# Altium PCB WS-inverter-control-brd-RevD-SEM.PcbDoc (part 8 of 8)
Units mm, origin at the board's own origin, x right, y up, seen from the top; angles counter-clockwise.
Board outline 270 x 105.92 mm, 6 copper layers (Top Layer, Int1 (Sign), Int2 (PWR), Int3 (GND), Int4 (Sign), Bottom Layer), stack 1.509 mm thick; 709 components, 375 nets, 2377 pads, 1332 vias.
Unrouted connection lines stored in the file: 55.
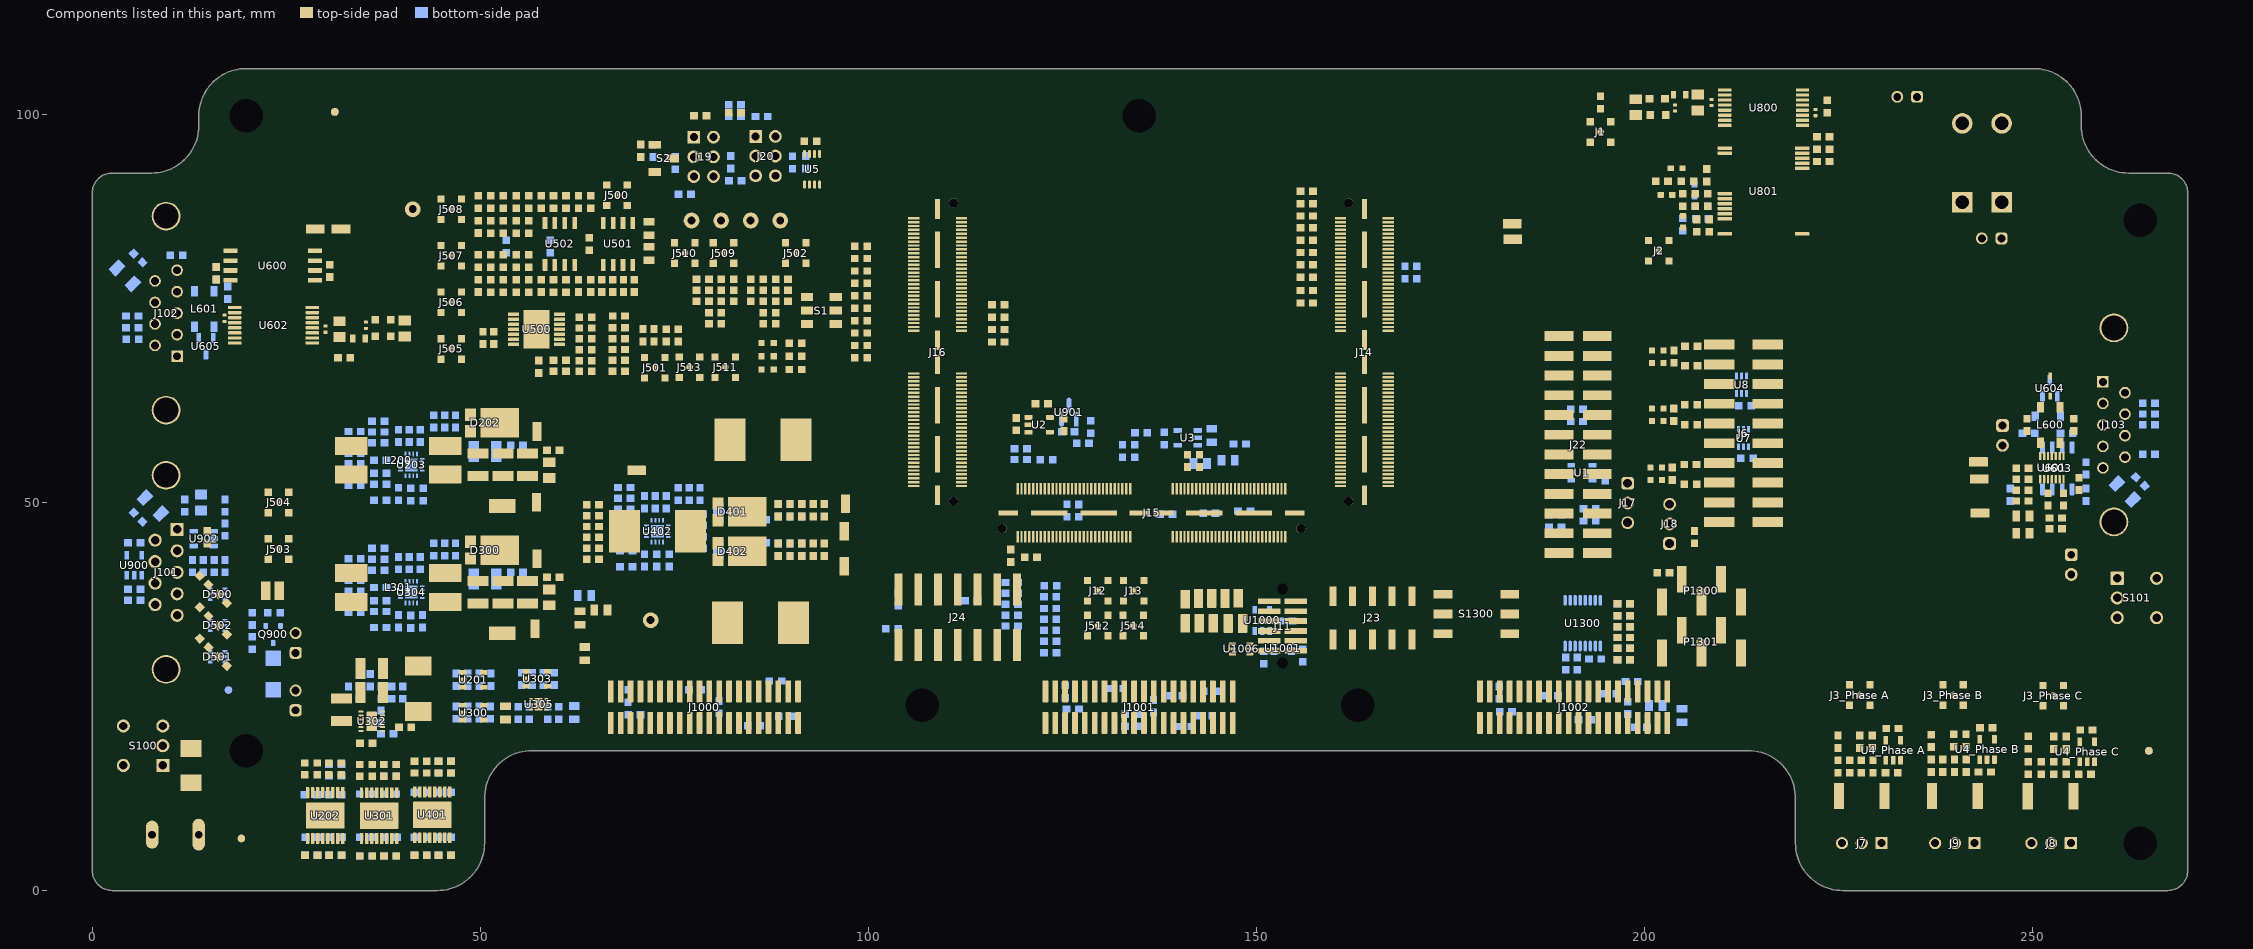
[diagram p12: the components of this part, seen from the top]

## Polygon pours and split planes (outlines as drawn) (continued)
GND on Top Layer "TOP_LAYER_GND_P448" (solid, remove dead copper, pour order 448): 29.692,48.725 30.942,47.475 57.192,47.475 61.192,51.475 61.192,59.475 56.692,63.975 31.192,63.975 29.692,62.475
+3.3V on Top Layer "TOP_LAYER_+3.3V_P446" (solid, remove dead copper, pour order 446): 183.868,55.069 188.268,55.069 188.268,56.04 183.868,56.04
NetD3_1 on Top Layer "TOP_LAYER_NETD3_1_P443" (solid, remove dead copper, pour order 443): 183.943,59.636 183.943,56.936 184.864,56.936 184.864,59.636
NetD2_1 on Top Layer "TOP_LAYER_NETD2_1_P444" (solid, remove dead copper, pour order 444): 185.643,59.636 185.643,56.936 186.605,56.936 186.605,59.636
NetD1_1 on Top Layer "TOP_LAYER_NETD1_1_P445" (solid, remove dead copper, pour order 445): 187.343,59.636 187.343,56.936 188.278,56.936 188.278,59.636
NetC606_1 on Top Layer "TOP_LAYER_NETC606_1_P441" (solid, remove dead copper, pour order 441): 27.493,72.066 27.493,71.006 29.193,71.006 29.193,72.066
+5V_ISO on Top Layer "TOP_LAYER_+5V_ISO_P436" (solid, remove dead copper, pour order 436): 17.493,75.267 17.493,73.656 19.193,73.656 19.193,75.267
NetC800_1 on Top Layer "TOP_LAYER_NETC800_1_P434" (solid, remove dead copper, pour order 434): 209.515,102.701 209.515,101.683 209.535,101.662 211.186,101.662 211.186,102.694
Pgndin_1 on Top Layer "TOP_LAYER_PGNDIN_1_P432" (solid, remove dead copper, pour order 432): 218.85,104.554 218.85,92.136 247.763,92.136 247.763,104.539
5V_iso_AMC_9 on Top Layer "TOP_LAYER_5V_ISO_AMC_9_P431" (solid, remove dead copper, pour order 431): 219.515,100.079 221.186,100.079 221.186,98.398 219.515,98.398
+5V on Top Layer "TOP_LAYER_+5V_P369" (solid, remove dead copper, pour order 369): 54.083,29.081 54.351,29.35 57.114,29.35 57.383,29.081 57.383,27.6 54.083,27.6
+5V on Top Layer "TOP_LAYER_+5V_P372" (solid, remove dead copper, pour order 372): 54.169,24.994 54.25,25.075 56.65,25.075 56.85,24.875 56.85,23.475 56.55,23.175 54.25,23.175 54.169,23.256
+3.3V_C-V on Top Layer "TOP_LAYER_+3.3V_C-V_P374" (solid, remove dead copper, pour order 374): 231.55,19.325 231.575,19.325 232.45,20.2 233.775,20.2 233.775,18.525 233.5,18.25 231.55,18.25 231.55,18.463
NetC411_1 on Top Layer "TOP_LAYER_NETC411_1_P376" (solid, remove dead copper, pour order 376): 73.475,47.625 74.2,48.35 75.7,48.35 75.975,48.075 75.975,46.175 75.75,45.95 74.125,45.95 73.475,46.6
+12V_H on Top Layer "TOP_LAYER_+12V_H_P377" (solid, pour order 377): 27.6,11.763 27.5,11.863 27.5,13.963 28.4,15.063 28.4,17.763 28.7,18.063 30.8,18.063 31,17.863 31,14.463 30.8,14.263 29,14.263 28.6,13.863 28.6,11.863 28.5,11.763
+12V_L on Top Layer "TOP_LAYER_+12V_L_P378" (solid, pour order 378): 34.557,11.743 34.457,11.843 34.457,13.943 35.357,15.043 35.357,17.743 35.657,18.043 37.857,18.043 38.157,17.743 38.157,14.198 38.102,14.143 35.857,14.143 35.557,13.843 35.557,11.843 35.457,11.743
+12V_LEM on Top Layer "TOP_LAYER_+12V_LEM_P379" (solid, pour order 379): 41.4,11.843 41.3,11.943 41.3,14.043 42.5,15.509 42.5,17.843 42.8,18.143 44.9,18.143 45.2,17.843 45.2,14.498 44.944,14.243 42.7,14.243 42.4,13.943 42.4,11.943 42.3,11.843
+12V_H on Top Layer "TOP_LAYER_+12V_H_P380" (solid, remove dead copper, pour order 380): 30.3,60.15 33.9,60.15 35.6,58.45 35.6,56.05 34.8,55.25 30.3,55.25
GND on Top Layer "TOP_LAYER_GND_P382" (solid, remove dead copper, pour order 382): 29.75,48.75 31,47.5 57.25,47.5 61.25,51.5 61.25,59.5 56.75,64 31.25,64 29.75,62.5
+12V_L on Top Layer "TOP_LAYER_+12V_L_P383" (solid, remove dead copper, pour order 383): 30.3,43.75 33.8,43.75 35.5,42.05 35.5,39.65 34.7,38.85 30.3,38.85
+12V_LEM on Top Layer "TOP_LAYER_+12V_LEM_P384" (solid, remove dead copper, pour order 384): 64.4,50.8 65.2,51.6 66.1,51.6 68.8,48.9 68.8,43.8 65.9,40.9 65.2,40.9 64.4,41.7
NetC411_2 on Top Layer "TOP_LAYER_NETC411_2_P385" (solid, remove dead copper, pour order 385): 79,59.9 80.3,61.2 84,61.2 84.42,60.78 84.42,49.82 81.6,47 79.9,47 79,47.9
+15V on Top Layer "TOP_LAYER_+15V_P386" (solid, remove dead copper, pour order 386): 81.7,50.5 82.4,51.2 97.7,51.2 97.9,51 97.9,48.929 97.871,48.9 89.1,48.9 86.6,46.4 83,46.4 81.7,47.7
NetC430_2 on Top Layer "TOP_LAYER_NETC430_2_P389" (solid, remove dead copper, pour order 389): 79.1,32.3 79.1,45.3 79.9,46.1 81.8,46.1 84.6,43.3 84.6,32.3 83.5,31.2 80.2,31.2
GND on Top Layer "TOP_LAYER_GND_P390" (solid, remove dead copper, pour order 390): 62.32,39.5 78.75,39.5 78.75,30.8 87.743,30.731 87.743,43.6 98.107,43.6 99.943,45.436 99.943,57.307 94.5,62.75 68.75,62.75 62.32,56.32
+3.3V_C-V_LDO on Top Layer "TOP_LAYER_+3.3V_C-V_LDO_P398" (solid, remove dead copper, pour order 398): 58.05,24.875 58.25,25.075 60.65,25.075 60.85,24.875 60.85,23.475 60.55,23.175 58.25,23.175 58.05,23.375
+3.3V_L on Top Layer "TOP_LAYER_+3.3V_L_P399" (solid, remove dead copper, pour order 399): 49.783,24.842 49.983,25.042 53.658,25.042 53.948,24.752 53.948,23.261 53.829,23.142 49.983,23.142 49.783,23.342
+12V_L on Top Layer "TOP_LAYER_+12V_L_P400" (solid, remove dead copper, pour order 400): 45.475,24.675 45.7,24.9 48.05,24.9 48.275,24.675 48.275,23.25 47.975,22.95 45.675,22.95 45.475,23.15
+3.3V_H on Top Layer "TOP_LAYER_+3.3V_H_P401" (solid, remove dead copper, pour order 401): 49.5,29.25 49.7,29.45 52.575,29.45 52.775,29.25 52.775,27.75 52.575,27.55 49.7,27.55 49.5,27.75
+12V_H on Top Layer "TOP_LAYER_+12V_H_P404" (solid, remove dead copper, pour order 404): 45.5,29.25 45.7,29.45 48.1,29.45 48.3,29.25 48.3,27.85 48,27.55 45.7,27.55 45.5,27.75
GND on Top Layer "TOP_LAYER_GND_P405" (solid, remove dead copper, pour order 405): 11.2,15.175 11.625,15.6 13.8,15.6 14.15,15.25 14.15,13.15 13.775,12.775 11.525,12.775 11.2,13.1
+3.3V_LDO on Top Layer "Top Layer-+3.3V" (solid, remove dead copper, pour order 417): 60.357,29.35 61.507,30.5 65.8,30.5 62.7,27.4 60.75,27.4 60.531,27.181 57.783,27.181 57.583,27.381 57.583,29.081 57.851,29.35
+3.3V on Top Layer "Top Layer-+3.3V" (solid, remove dead copper, pour order 418): 64.707,33.9 61.507,30.7 67.143,30.7 67.143,33.9
VIN_12V_1 on Top Layer "Top Layer-VIN_12V" (solid, remove dead copper, pour order 423): 6.2,4 9.6,0.6 47.5,0.6 48.1,1.2 48.1,4.6 47.682,5.018 44.119,5.018 43.05,6.087 43.05,7.448 41.3,7.448 41.3,4.918 37.277,4.918 36.207,5.987 36.207,7.348 34.457,7.348 34.457,5.038 30.125,5.038 29.25,5.913 29.25,7.363 27.5,7.363 21.816,7.363 16.3,12.88 16.3,18.2 14.5,20 8.3,20 6.2,17.9
5V_iso_AMC_9 on Top Layer "TOP_LAYER_5V_ISO_AMC_9_P429" (solid, remove dead copper, pour order 429): 219.5,100.059 221.2,100.059 221.2,98.447 221.151,98.398 221.137,98.412 219.515,98.412
GND on Int1 (Sign) "INT1_(SIGN)_GND_P491" (solid, remove dead copper, pour order 491): 27.134,105.918 27.134,57.836 23.834,54.536 0,54.536 0,-2.664 50.58,-2.664 50.58,9.063 59.053,17.536 214.034,17.536 217.796,13.774 217.796,4.774 224.134,-1.564 270.002,-1.564 270.002,75.673 211.641,75.673 211.641,105.918
GND_ISO on Int1 (Sign) "INT1_(SIGN)_GND_ISO_P503" (solid, pour order 503): 19.643,75.636 25.843,75.636 25.843,70.036 19.243,70.036 19.243,62.136 16.943,59.836 16.843,59.848 0.45,59.848 0.45,91.843 1.643,93.036 16.043,93.036 19.643,89.436
+3.3V_C-V on Int1 (Sign) "INT1_(SIGN)_+3.3V_C-V_P490" (solid, remove dead copper, pour order 490): 65.238,26.847 61.343,22.951 61.343,20.036 63.943,20.036 63.943,22.236 72.643,30.936 85.743,30.936 85.743,33.036 71.243,33.036
+5V on Int1 (Sign) "INT1_(SIGN)_+5V_P481" (solid, remove dead copper, pour order 481): 50.25,31.5 57.168,38.418 63.418,38.418 68.5,43.5 78.75,43.5 78.75,39.5 68.407,39.5 59.157,30.25 50.25,30.25
+3.3V on Int4 (Sign) "INT4_(SIGN)_+3.3V_P495" (solid, remove dead copper, pour order 495): 71.738,79.336 79.043,79.336 79.043,81.811 71.738,81.811
+5V on Int4 (Sign) "INT4_(SIGN)_+5V_P483" (solid, remove dead copper, pour order 483): 53.943,27.836 55.217,27.836 55.943,28.563 55.943,30.736 53.943,30.736
+5V on Int4 (Sign) "INT4_(SIGN)_+5V_P482" (solid, remove dead copper, pour order 482): 36.943,29.436 36.943,27.368 39.675,27.368 39.675,30.136 56.85,30.136 56.85,31.036 36.943,31.036
+5V on Int4 (Sign) "INT4_(SIGN)_+5V_P479" (solid, remove dead copper, pour order 479): 76.843,43.736 76.843,39.836 78.743,39.836 78.743,57.969 109.143,57.969 109.143,60.636 76.843,60.636

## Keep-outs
Top Layer:
  rectangle: 30.55,5.581 31.4,6.831
  rectangle: 37.507,5.561 38.357,6.811
  rectangle: 44.35,5.661 45.2,6.911
  lines w0.25: 26.613,75.909 26.613,76.136 28.771,76.136 31.643,76.136 33.243,74.536 41.379,74.536 ; 26.631,69.136 27.343,69.136 28.092,69.136 28.892,69.936 29.143,69.936 39.143,69.936 ; 199.743,98.936 204.84,98.939 206.843,96.936 211.964,96.936 212.136,97.109 212.136,98.036 ; 200.25,103.144 200.743,103.636 207.843,103.636 208.643,104.436 208.788,104.436 210.643,104.436 212.194,104.436
  lines w0.35: -1.351,59.536 17.626,59.536 19.943,61.853 19.943,89.536 16.443,93.036 7.943,93.036 ; -1.179,55.877 23.605,55.877 26.604,58.875 26.604,94.436 ; 212.043,107.036 212.043,76.735 212.242,76.536 272.743,76.536 ; 212.191,106.932 212.191,76.631 212.39,76.432 272.891,76.432 ; 218.85,91.835 229.173,91.835 231.874,94.536 256.443,94.536
  lines w0.5: 29.75,30.6 44.25,30.6 ; 32.7,18.1 29.75,21.05 29.75,29.25 29.75,32.75 29.75,34 29.75,38.75 29.75,46.25 31,47.5 ; 37.3,18.5 40.7,18.5 41.7,19.5 43,19.5 44.25,20.75 44.25,26.25 44.25,29.5 44.25,30.6 ; 61.25,57.002 63.002,57.002 68.75,62.75 94.5,62.75 94.85,62.4 100.25,57 100.25,51.25 100.25,48.5 ; 62.32,39.5 62.32,57.002 ; 99.25,39.5 93.5,33.75 93.5,30.664 86.75,30.664 86.75,39.25 85.75,39.25 85.25,39.25 85.25,30.75 78.75,30.75 78.75,34.25 78.75,39.5 76.25,39.5 65.107,39.5 61.25,39.5 ; 31,47.5 57.25,47.5 ; 31,47.5 29.75,48.75 29.75,62.5 31.25,64 56.75,64 59.5,61.25 61.25,59.5 61.25,53.75 61.25,51.5 59.75,50 57.25,47.5 ; 44.25,30.6 55.6,30.6 56.85,30.6 60,33.75 61.25,35 61.25,39.5 ; 57.25,47.5 61.25,43.5 61.25,39.5
Int2 (PWR):
  lines w0.35: -1.351,59.536 17.459,59.536 19.943,62.021 19.943,89.704 16.443,93.204 7.943,93.204 ; -1.179,55.806 23.605,55.806 26.604,58.804 26.604,94.365 ; 212.151,107.036 212.151,76.735 212.349,76.536 272.851,76.536
Int3 (GND):
  lines w0.35: -1.351,59.536 17.613,59.536 19.943,61.867 19.943,89.55 16.443,93.05 7.943,93.05 ; -1.179,55.921 23.605,55.921 26.604,58.92 26.604,94.481 ; 212.191,107.036 212.191,76.735 212.39,76.536 272.891,76.536
Int1 (Sign):
  lines w0.35: -1.351,59.536 17.62,59.536 19.943,61.86 ; -1.179,55.851 23.605,55.851 26.604,58.85 26.604,94.411 ; 7.943,93.043 16.443,93.043 19.943,89.543 ; 212.151,106.993 212.151,76.691 212.349,76.493 272.851,76.493
Int4 (Sign):
  lines w0.35: -1.351,59.512 -1.326,59.536 17.586,59.536 19.943,61.894 19.943,89.577 16.443,93.077 7.943,93.077 ; -1.179,55.898 23.605,55.898 26.604,58.897 26.604,94.458
Bottom Layer:
  circle w4: c134.874,99.822 r4
  circle w4: c19.812,99.822 r4
  circle w4: c263.906,6.096 r4
  circle w4: c263.906,86.36 r4
  circle w4: c163.068,23.876 r4
  circle w4: c106.934,23.876 r4
  circle w4: c19.812,18.034 r4
  region: 82.906,52.494 84.3,51.1 86.991,51.1 86.991,45.961 86.3,45.27 86.3,44.33 87,43.63 87,39.5 82.906,39.5
  lines w0.35: -1.351,59.536 17.514,59.536 19.943,61.965 19.943,89.648 16.443,93.148 7.943,93.148 ; -1.179,55.926 23.605,55.926 26.604,58.925 26.604,94.485 ; 212.195,106.932 212.195,76.631 212.393,76.432 272.895,76.432
  lines w0.5: 32.75,30.6 29.75,30.6 ; 61.25,57.002 63.002,57.002 68.75,62.75 94.5,62.75 100.25,57 100.25,51.25 100.25,40.5 ; 62.32,39.5 62.32,57.002 ; 78.8,38.5 82.029,38.5 83.029,39.5 83.3,39.5 99.25,39.5 ; 99.375,44.4 99.25,39.5 ; 29.75,30.6 29.75,20.73 31.48,19 37.65,19 41.2,19 ; 29.75,30.6 44.25,30.6 ; 29.75,30.6 29.75,32.75 29.75,34 29.75,38.75 29.75,46.25 31,47.5 ; 31,47.5 29.75,48.75 29.75,62.5 31.25,64 56.75,64 59.5,61.25 61.25,59.5 61.25,53.75 61.25,51.5 59.75,50 57.25,47.5 ; 31,47.5 57.25,47.5 ; 41.2,19 41.7,19.5 43,19.5 44.25,20.75 44.25,26.25 44.25,29.5 44.25,30.6 ; 41.2,19 41.2,19 ; 44.25,30.6 55.6,30.6 56.85,30.6 60,33.75 61.25,35 61.25,39.5 ; 57.25,47.5 61.25,43.5 61.25,39.5 ; 61.25,39.5 65.107,39.5 78.5,39.5 78.5,34.5 78.5,30.75 93.5,30.75 93.5,33.75 99.25,39.5
Keep-Out Layer:
  circle w1.5: c134.874,99.822 r3.25
  circle w1.5: c19.812,18.034 r3.25
  circle w1.5: c19.812,99.822 r3.25
  circle w1.5: c263.906,86.36 r3.25
  circle w1.5: c263.906,6.096 r3.25
  circle w1.5: c163.068,23.876 r3.25
  circle w1.5: c106.934,23.876 r3.25

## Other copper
Top Layer:
  region net +15V: 54.939,71.436 ccw(c54.939,71.486) 54.988,71.486 54.988,73.137 ccw(c54.939,73.137) 54.939,73.186 52.438,73.186 52.438,72.511 49.863,72.511 49.863,71.436 53.638,71.436
  pour cut-out: 36.693,74.836 41.593,74.836 41.593,72.436 36.693,72.436
  pour cut-out: 197.743,100.636 202.643,100.636 202.643,98.236 197.743,98.236
  region net GND: 36.65,23.65 36.2,24.1 36.2,30.126 30.75,30.126 30.75,24.1 33.45,24.1 34.05,23.5 34.9,23.5 35.35,23.05 35.35,18.78 35.605,18.525 36.65,18.525
  pour cut-out: 29.75,30.6 44.25,30.6 44.25,20.75 43,19.5 41.7,19.5 41.2,19 31.8,19 29.75,21.05
  region net +12V_L: 34.4,17.1 37.6,17.1 37.6,18 35.7,18 35,18.7 35,20.566 34.891,20.675 34.225,20.675 34,20.9 34,21.2 34.225,21.425 34.61,21.425 34.61,21.675 34.275,21.675 33.45,22.5 30.75,22.5 30.75,20.75 32.025,19.475
  region net +5V: 36.8,24.15 39.15,24.15 41,26 43,26 43.714,26.714 43.714,30.126 36.8,30.126
  region net NetC312_2: 37.13,20.675 37.671,20.675 37.987,20.359 40.285,20.359 40.285,24.286 43.714,24.286 43.714,20.914 42.8,20 41.5,20 40.8,19.3 37.08,19.3 37.08,20.625
  region net NetC323_2: 48.1,38.85 48.1,35.55 43.4,35.55 43.1,35.85 43.1,38.65 43.4,38.95 43.893,38.95 44.017,38.826 44.201,38.75 44.399,38.75 44.583,38.826 44.707,38.95 45.293,38.95 45.417,38.826 45.601,38.75 45.799,38.75 45.983,38.826 46.107,38.95 46.693,38.95 46.817,38.826 47.001,38.75 47.199,38.75 47.383,38.826 47.507,38.95 48,38.95
  region net NetC323_1: 49.5,45.754 49.5,41.67 49.496,41.652 49.486,41.636 48.618,40.768 48.603,40.758 48.584,40.754 48.356,40.754 48.316,40.746 48.276,40.738 48.242,40.715 48.241,40.715 48.208,40.692 48.185,40.659 48.185,40.658 48.162,40.624 48.146,40.543 48.146,40.316 48.142,40.297 48.132,40.282 47.005,39.155 46.802,39.155 46.683,39.274 46.499,39.35 46.301,39.35 46.117,39.274 45.993,39.15 45.407,39.15 45.283,39.274 45.099,39.35 44.901,39.35 44.717,39.274 44.593,39.15 44.007,39.15 43.883,39.274 43.699,39.35 43.501,39.35 43.5,39.35 43.1,39.75 43.1,41.95 47,45.85 49.34,45.85
  region net NetC316_1: 56.6,44.15 57.805,44.15 59.213,42.748 59.213,40.037 59.8,39.45 59.8,38.262 59.688,38.15 56.9,38.15 55.9,39.15 48.4,39.15 48.1,39.45 48.1,39.962 48.29,40.152 48.334,40.218 48.35,40.296 48.35,40.523 48.354,40.544 48.355,40.545 48.355,40.546 48.377,40.55 48.604,40.55 48.682,40.566 48.748,40.61 49.644,41.506 49.688,41.572 49.704,41.65 49.704,45.754 50.1,46.15 54.6,46.15
  region net +24V_H: 56.7,60.55 57.905,60.55 59.313,59.148 59.313,56.437 59.502,56.248 59.512,56.2 59.557,56.132 59.625,56.087 59.673,56.077 59.9,55.85 59.9,54.709 59.741,54.55 57,54.55 56,55.55 48.45,55.55 48.2,55.8 48.2,56.362 48.29,56.452 48.334,56.518 48.35,56.596 48.35,56.923 48.354,56.944 48.355,56.945 48.355,56.946 48.377,56.95 48.704,56.95 48.782,56.966 48.848,57.01 49.744,57.906 49.788,57.972 49.804,58.05 49.804,61.95 49.8,61.97 49.8,62.15 50.2,62.55 54.7,62.55
  region net NetC226_2: 43.893,55.35 44.017,55.226 44.201,55.15 44.399,55.15 44.583,55.226 44.707,55.35 45.293,55.35 45.417,55.226 45.601,55.15 45.799,55.15 45.983,55.226 46.107,55.35 46.693,55.35 46.817,55.226 47.001,55.15 47.199,55.15 47.383,55.226 47.507,55.35 47.984,55.35 48.1,55.234 48.1,51.95 43.5,51.95 43.2,52.25 43.2,55.05 43.5,55.35
  region net NetC226_1: 49.6,61.95 49.6,58.05 48.704,57.154 48.356,57.154 48.276,57.138 48.208,57.092 48.162,57.024 48.146,56.943 48.146,56.596 47.1,55.55 46.807,55.55 46.683,55.674 46.499,55.75 46.301,55.75 46.117,55.674 45.993,55.55 45.407,55.55 45.283,55.674 45.099,55.75 44.901,55.75 44.717,55.674 44.593,55.55 44.007,55.55 43.883,55.674 43.699,55.75 43.6,55.75 43.2,56.15 43.2,58.35 47.1,62.25 49.3,62.25
  text ".Layer_Name" at 9.576,-47.206 h1.52
Int2 (PWR):
  text ".Layer_Name" at 9.576,-47.206 h1.52
Int3 (GND):
  region net AGND_C: 73.8,51.2 73.8,50.2 73.5,49.9 69.1,49.9 68.8,49.6 68.8,43.2 68.1,42.5 67.2,42.5 66.9,42.8 66.9,50.898 67.602,51.6 73.4,51.6
  region net AGND_B: 42.1,43.35 42.1,42.35 41.8,42.05 38.6,42.05 38.2,41.65 38.2,40.05 39.2,39.05 39.3,38.95 39.3,38.45 39.2,38.35 38.5,38.35 38.2,38.05 38.2,34.65 38,34.45 36.6,34.45 36,35.05 36,43.65 36.1,43.75 41.7,43.75
  region net AGND_A: 42.1,59.75 42.1,58.75 41.8,58.45 38.6,58.45 38.2,58.05 38.2,56.45 39.2,55.45 39.3,55.35 39.3,54.85 39.2,54.75 38.5,54.75 38.2,54.45 38.2,51.05 38,50.85 36.6,50.85 36,51.45 36,60.05 36.1,60.15 41.7,60.15
  text ".Layer_Name" at 9.576,-47.206 h1.52
Int1 (Sign):
  text ".Layer_Name" at 9.576,-47.206 h1.52
Int4 (Sign):
  text ".Layer_Name" at 9.576,-47.206 h1.52
Bottom Layer:
  region net +5V: 35.33,28.4 36.23,29.3 39.6,29.3 39.6,27.3 35.43,27.3 35.33,27.4
  region net +15V: 95.5,51.2 95.5,49.5 95,49 88,49 87.4,49.6 87.4,51.2 87.9,51.7 95,51.7
  region net -15V: 94.898,43.996 94.914,43.986 95.15,43.75 95.244,43.656 95.386,43.514 95.396,43.498 95.4,43.48 95.4,42.506 95.4,41.902 95.4,41.8 94.9,41.3 87.92,41.3 87.902,41.304 87.886,41.314 87.314,41.886 87.304,41.902 87.3,41.92 87.3,43.48 87.304,43.498 87.314,43.514 87.786,43.986 87.802,43.996 87.82,44 87.889,44 87.91,44 87.929,43.996 87.93,43.996 88.87,43.996 88.871,43.996 88.89,44 88.911,44 89.389,44 89.41,44 89.429,43.996 89.43,43.996 90.37,43.996 90.371,43.996 90.39,44 90.41,44 90.889,44 90.91,44 90.929,43.996 90.93,43.996 91.87,43.996 91.871,43.996 91.89,44 91.91,44 94.88,44
  region net GND: 87.922,48.812 88,48.796 95,48.796 95.078,48.812 95.144,48.856 95.318,48.782 97.1,47 97.1,45.2 95.7,43.8 95.388,43.8 95.044,44.144 94.978,44.188 94.9,44.204 91.89,44.204 91.871,44.2 91.851,44.2 91.85,44.2 90.95,44.2 90.949,44.2 90.929,44.2 90.91,44.204 90.39,44.204 90.371,44.2 90.351,44.2 90.35,44.2 89.45,44.2 89.449,44.2 89.429,44.2 89.41,44.204 88.89,44.204 88.871,44.2 88.851,44.2 88.85,44.2 87.95,44.2 87.949,44.2 87.929,44.2 87.91,44.204 87.8,44.204 87.797,44.203 87.5,44.5 87.5,47.31 87.504,47.33 87.504,48.27 87.5,48.29 87.5,48.5 87.856,48.856
  region net NetC430_2: 82.1,45.196 82.1,39.22 81.839,38.959 78.959,38.959 78.959,39.5 78.924,39.676 78.824,39.824 78.816,39.83 78.681,39.942 78.732,40.109 78.743,40.137 78.743,40.336 78.667,40.52 78.575,40.611 78.667,40.703 78.743,40.887 78.743,41.086 78.667,41.27 78.575,41.361 78.667,41.453 78.743,41.637 78.743,41.836 78.667,42.02 78.575,42.111 78.667,42.203 78.743,42.387 78.743,42.586 78.667,42.77 78.526,42.91 78.343,42.986 78.144,42.986 77.96,42.91 77.9,42.85 77.7,42.933 77.7,43.396 77.778,43.412 77.844,43.456 78.044,43.656 78.088,43.722 78.104,43.8 78.104,45.951 78.138,45.998 78.263,46.104 78.3,46.096 81.2,46.096
  region net NetC411_2: 82.1,52.867 82.1,47.2 81.2,46.3 78.3,46.3 78.104,46.496 78.104,48.8 78.088,48.878 78.044,48.944 77.9,49.088 77.9,49.596 78.77,49.596 78.85,49.612 78.918,49.657 78.963,49.725 78.979,49.805 78.979,50.795 78.963,50.875 78.918,50.943 78.85,50.988 78.77,51.004 78.77,51.196 78.85,51.212 78.918,51.257 78.963,51.325 78.979,51.405 78.979,52.395 78.963,52.475 78.918,52.543 78.85,52.588 78.77,52.604 78.606,52.604 78.606,52.873 79.227,53.494 81.473,53.494
  region net NetC411_1: 77.9,48.8 77.9,43.8 77.7,43.6 76.4,43.6 74.658,45.342 74.685,45.383 74.705,45.48 74.705,45.62 74.685,45.717 74.63,45.8 74.685,45.883 74.705,45.98 74.705,46.12 74.685,46.217 74.63,46.3 74.547,46.355 74.45,46.375 73.95,46.375 73.835,46.556 73.835,47.08 73.816,47.178 73.76,47.26 73.678,47.316 73.58,47.335 73.556,47.335 73.375,47.45 73.375,47.715 73.376,47.72 73.376,47.908 73.662,48.194 73.7,48.194 73.817,48.217 73.916,48.284 74.165,48.532 74.413,48.532 74.493,48.548 74.561,48.594 74.606,48.661 74.622,48.741 74.622,49 77.7,49
  region net NetC226_1: 48.494,59.25 48.5,59.249 48.505,59.245 48.506,59.244 49.994,57.756 49.998,57.749 50,57.741 50,55.359 49.998,55.351 49.994,55.344 49.806,55.156 49.799,55.152 49.791,55.15 48.405,55.15 48.3,55.255 48.3,55.299 48.281,55.396 48.243,55.487 48.188,55.569 48.119,55.638 48.037,55.693 47.946,55.731 47.849,55.75 47.751,55.75 47.654,55.731 47.563,55.693 47.499,55.65 46.701,55.65 46.637,55.693 46.546,55.731 46.449,55.75 46.351,55.75 46.254,55.731 46.163,55.693 46.099,55.65 45.301,55.65 45.237,55.693 45.146,55.731 45.049,55.75 44.951,55.75 44.854,55.731 44.763,55.693 44.699,55.65 44,55.65 43.5,56.15 43.5,58.25 43.7,58.45 46.6,58.45 47.098,58.948 47.27,58.948 47.324,58.955 47.374,58.976 47.416,59.009 47.449,59.051 47.47,59.101 47.477,59.155 47.572,59.25
  region net NetC323_1: 201 vertices and 0 holes, not listed, extent 43.5,38.75 49.802,42.648
  region net NetC323_2: 43.8,39.25 43.8,39.201 43.819,39.104 43.857,39.013 43.912,38.931 43.981,38.862 44.063,38.807 44.154,38.769 44.251,38.75 44.349,38.75 44.446,38.769 44.537,38.807 44.619,38.862 44.688,38.931 44.701,38.95 45.299,38.95 45.312,38.931 45.381,38.862 45.463,38.807 45.554,38.769 45.651,38.75 45.749,38.75 45.846,38.769 45.937,38.807 46.019,38.862 46.088,38.931 46.101,38.95 46.699,38.95 46.712,38.931 46.781,38.862 46.863,38.807 46.954,38.769 47.051,38.75 47.149,38.75 47.246,38.769 47.337,38.807 47.419,38.862 47.488,38.931 47.501,38.95 48,38.95 48.5,38.45 48.5,36.616 48.489,36.591 47.659,35.761 47.634,35.75 43.715,35.75 43.689,35.761 43.2,36.25 43.2,38.155 42.975,38.381 42.968,38.396 42.928,38.448 42.876,38.488 42.815,38.514 42.75,38.522 42.278,38.522 42.145,38.654 42.14,38.667 42.135,38.68 42.134,38.685 42.133,38.704 42.133,38.705 42.133,39.06 42.132,39.064 42.133,39.068 42.132,39.078 42.132,39.23 42.125,39.282 42.4,39.55 43.5,39.55
  region net NetC226_2: 43.809,55.556 43.819,55.504 43.857,55.413 43.912,55.331 43.981,55.262 44.063,55.207 44.154,55.169 44.251,55.15 44.349,55.15 44.446,55.169 44.537,55.207 44.619,55.262 44.688,55.331 44.743,55.413 44.762,55.459 44.764,55.459 44.781,55.468 44.8,55.475 44.805,55.479 44.811,55.482 44.859,55.514 44.913,55.537 44.971,55.548 45.029,55.548 45.087,55.537 45.141,55.514 45.189,55.482 45.195,55.479 45.2,55.475 45.219,55.468 45.236,55.459 45.238,55.459 45.257,55.413 45.312,55.331 45.381,55.262 45.463,55.207 45.554,55.169 45.651,55.15 45.749,55.15 45.846,55.169 45.937,55.207 46.019,55.262 46.088,55.331 46.143,55.413 46.162,55.459 46.164,55.459 46.181,55.468 46.2,55.475 46.205,55.479 46.211,55.482 46.259,55.514 46.313,55.537 46.371,55.548 46.429,55.548 46.487,55.537 46.541,55.514 46.589,55.482 46.595,55.479 46.6,55.475 46.619,55.468 46.636,55.459 46.638,55.459 46.657,55.413 46.712,55.331 46.781,55.262 46.863,55.207 46.954,55.169 47.051,55.15 47.149,55.15 47.246,55.169 47.337,55.207 47.419,55.262 47.488,55.331 47.543,55.413 47.562,55.459 47.564,55.459 47.581,55.468 47.6,55.475 47.605,55.479 47.611,55.482 47.659,55.514 47.713,55.537 47.771,55.548 47.802,55.548 48.099,55.251 48.105,55.202 48.125,55.154 48.157,55.112 48.262,55.007 48.304,54.975 48.352,54.955 48.401,54.949 48.5,54.85 48.5,53.01 48.498,53.002 48.494,52.995 47.655,52.156 47.648,52.152 47.64,52.15 43.709,52.15 43.701,52.152 43.694,52.156 43.2,52.65 43.2,54.555 42.975,54.781 42.968,54.796 42.928,54.848 42.876,54.888 42.815,54.914 42.75,54.922 42.328,54.922 42.301,54.949 42.141,55.108 42.137,55.115 42.133,55.134 42.133,55.46 42.132,55.464 42.133,55.468 42.132,55.478 42.132,55.63 42.125,55.682 42.4,55.95 43.415,55.95
  region net +12V_H: 33.7,59.425 33.7,51.55 32.705,51.55 32.3,51.955 32.3,54.6 31.65,55.25 30.209,55.25 30.209,60.25 32.875,60.25
  region net +12V_L: 33.7,43.025 33.7,35.15 32.705,35.15 32.3,35.555 32.3,38.2 31.65,38.85 30.209,38.85 30.209,43.85 32.875,43.85
  region net NetC100_1: 9.5,51.65 9.5,55.35 0.5,55.35 0.5,26.65 9.5,26.65 9.5,30.35 2.538,37.312 2.538,45.038 6.9,49.4 9.15,51.65
  region net NetC101_1: 9.5,85.05 9.5,88.75 0.5,88.75 0.5,60.05 9.5,60.05 9.5,63.75 2.538,70.712 2.538,78.438 6.9,82.8 9.15,85.05
  region net NetC102_1: 260.5,49.35 260.5,45.65 269.5,45.65 269.5,74.35 260.5,74.35 260.5,70.65 267.462,63.688 267.462,55.962 263.1,51.6 260.85,49.35
  text ".Layer_Name" at 9.576,-47.206 h1.52

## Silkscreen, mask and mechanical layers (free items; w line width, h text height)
Top Overlay:
  lines w0.152: 11.75,0.75 20.25,0.75 20.25,2.75 19.25,3.75 ; 229.75,23 231.5,23 231.5,27 229.75,27 ; 241.75,23 243.5,23 243.5,27 241.75,27 ; 253.75,21.5 255.5,21.5 ; 254.89,26.933 256.64,26.933 256.64,22.933
  lines w0.25: 101.049,41.178 101.049,104.677 101.05,104.678 180.05,104.678 180.05,41.178 ; 101.05,41.178 180.05,41.178 ; 180.05,41.178 180.05,41.178
  lines w0.254: 209.61,82.232 212.15,82.232 ; 210.626,81.724 212.15,82.232 ; 210.626,82.74 212.15,82.232 ; 212.15,81.978 212.15,82.486 ; 218.55,81.978 218.55,82.486 ; 220.074,81.724 218.55,82.232 ; 220.074,82.74 218.55,82.232 ; 221.09,82.232 218.55,82.232 ; 229.879,93.528 232.419,93.528 ; 231.419,93.195 232.419,93.528 ; 231.419,93.862 232.419,93.528 ; 232.419,93.274 232.419,93.782 ; 236.919,93.274 236.919,93.782 ; 237.919,93.195 236.919,93.528 ; 237.919,93.862 236.919,93.528 ; 239.459,93.528 236.919,93.528 ; 247.621,94.03 247.621,94.538 ; 248.621,93.951 247.621,94.284 ; 248.621,94.617 247.621,94.284 ; 248.81,94.284 247.621,94.284 ; 249.547,74.932 250.055,76.456 ; 249.547,84.38 250.055,82.856 ; 249.801,76.456 250.309,76.456 ; 249.801,82.856 250.309,82.856 ; 250.055,73.916 250.055,76.456 ; 250.055,85.396 250.055,82.856 ; 250.563,74.932 250.055,76.456 ; 250.563,84.38 250.055,82.856 ; 252.832,94.284 254.021,94.284 ; 253.021,93.951 254.021,94.284 ; 253.021,94.617 254.021,94.284 ; 253.942,90.454 254.276,91.454 ; 253.942,96.954 254.276,95.954 ; 254.021,94.03 254.021,94.538 ; 254.022,91.454 254.53,91.454 ; 254.022,95.954 254.53,95.954 ; 254.276,88.914 254.276,91.454 ; 254.276,98.494 254.276,95.954 ; 254.609,90.454 254.276,91.454 ; 254.609,96.954 254.276,95.954
  lines w0.35: 0.53,58.636 16.726,58.636 19.943,61.853 19.943,86.836 19.943,89.536 16.443,93.036 12.043,93.036 ; 26.604,58.875 26.604,61.177 ; 26.604,60.896 26.604,89.396 26.604,94.436
  lines w0.5: 212.126,104.754 212.15,76.678 212.25,76.478 249.496,76.478 257.95,76.478 ; 218.526,104.554 218.526,82.768 257.85,82.878
  text "PGND" at 232.287,98.369 h1.5
  text "PGND" at 249,98.369 h1.5
  text "6.4 (mm)" at 249.064,93.864 h1
  text "TIDM-02014 revD" at 35.743,93.736 h2
  text "4.5 (mm)" at 255.955,91.936 h1 r90
  text "4.5 (mm)" at 232.901,91.849 h1
  text "N-O" at 71.527,90.936 h1.5 r90
  text "HV!" at 233.916,88.269 h1.5
  text "HV!" at 249,88.269 h1.5
  text "GND" at 39.291,86.551 h0.89 r90
  text "ISO-CAN" at 14.127,84.336 h1.5 r90
  text "6.4 (mm)" at 212.672,79.672 h1.52
  text "DANGER HIGH VOLTAGE!" at 224.359,78.483 h2.5
  text "6.4 (mm)" at 252.615,76.978 h1.52 r90
  text "CAN" at 256.927,71.636 h1.5 r90
  text "High Density Connector 2" at 113.948,60.936 h1.5 r90
  text "High Density Connector 3" at 159.548,58.236 h1.5 r90
  text "SW" at 69.296,55.489 h0.89
  text "CAN_TX" at 239.991,51.28 h1.5
  text "CAN_RX" at 240.046,49.732 h1.5
  text "POS. SENSE" at 14.227,48.236 h1.5 r90
  text "High Density Connector 1" at 128.743,42.531 h1.5
  text "GND" at 70.721,32.092 h0.89
  text "Ext. 12V switch" at 255.696,30.989 h0.89
  text "Phase B" at 116.996,27.489 h0.76
  text "Phase C" at 172.946,27.489 h0.76
  text "Phase A" at 61.096,27.289 h0.76
  text "I_A" at 231.07,23.889 h0.89 r90
  text "I_B" at 243.07,23.889 h0.89 r90
  text "I_C" at 256.211,23.822 h0.89 r90
  text "12VDC" at 16.427,4.936 h1.5 r90
  text ".Layer_Name" at 9.576,-47.206 h1.52
Bottom Overlay:
  text "PGND" at 238.391,98.475 h1.5
  text "PGND" at 254.443,98.454 h1.5
  text "HV!" at 238.2,88.3 h1.5
  text "HV!" at 252.843,88.136 h1.5
  text ".Layer_Name" at 9.576,-47.206 h1.52
Top Paste:
  text ".Layer_Name" at 9.576,-47.206 h1.52
Bottom Paste:
  text ".Layer_Name" at 9.576,-47.206 h1.52
Top Solder:
  text ".Layer_Name" at 9.576,-47.206 h1.52
  text ".Layer_Name" at 9.576,-47.206 h1.52
Bottom Solder:
  text ".Layer_Name" at 9.576,-47.206 h1.52
Drill Guide:
  text ".Layer_Name" at 9.576,-47.206 h1.52
M1 Board Outline:
  lines w0.254: 0,2.54 ccw(c2.54,2.54) 2.54,0 ; 0,2.54 ccw(c2.54,2.54) 2.54,0 ; 0,2.54 0,89.916 cw(c2.54,89.916) 2.54,92.456 7.62,92.456 ccw(c7.62,98.552) 13.716,98.552 13.716,99.822 cw(c19.812,99.822) 19.812,105.918 250.19,105.918 cw(c250.19,99.822) 256.286,99.822 256.286,98.552 ccw(c262.382,98.552) 262.382,92.456 267.462,92.456 cw(c267.462,89.916) 270.002,89.916 270.002,2.54 cw(c267.462,2.54) 267.462,0 225.552,0 cw(c225.552,6.096) 219.456,6.096 219.456,11.938 ccw(c213.36,11.938) 213.36,18.034 56.642,18.034 ccw(c56.642,11.938) 50.546,11.938 50.546,6.096 cw(c44.45,6.096) 44.45,0 2.54,0
  text ".Layer_Name" at 9.576,-47.206 h1.52
M2 Board Dimensions:
  rectangle: 3.175,-19.35 12.7,-16.175
  rectangle: 0,-16.175 3.175,-13
  lines w0.178: 0,-16.175 25.4,-16.175 ; 3.175,-19.35 3.175,-13 ; 6.35,-19.35 6.35,-13 ; 12.7,-19.35 12.7,-13 ; 19.05,-19.35 19.05,-13 ; 0,-19.35 25.4,-19.35 25.4,-13 0,-13 0,-19.35
  lines w0.254: 52.196,0 52.196,14 ; 105.196,0 105.196,14 ; 108.496,0 108.496,14 ; 161.496,0 161.496,14 ; 164.796,0 164.796,14 ; 217.796,0 217.796,14
  text ".Layer_Name" at 9.576,-47.206 h1.52
M3 3D STEP Top:
  text ".Layer_Name" at 9.576,-47.206 h1.52
M4 3D STEP Bottom:
  text ".Layer_Name" at 9.576,-47.206 h1.52
M5 Assembly Top:
  lines w0.254: -12.497,-49.026 155.143,-49.026 ; -12.497,-43.862 155.194,-43.862 ; -12.497,-38.697 -12.497,-54.191 89.23,-54.191 155.194,-54.191 155.194,-38.697 -12.484,-38.697 -12.484,-54.191 27.534,-54.191 ; 50.114,-54.191 50.114,-38.697 ; 82.296,-43.862 82.296,-38.697 ; 103.632,-43.862 103.632,-38.697 ; 119.431,-54.356 119.431,-49.204
  text "COMPONENTS MARKED 'DNP' SHOULD NOT BE POPULATED." at 24.219,-33.49 h1.52
  text "ASSEMBLY VARIANT:" at 24.206,-36.424 h1.52
  text ".VariantName" at 50.521,-36.424 h1.52
  text "PCB VIEWED FROM TOP SIDE" at -10.884,-42.054 h1.52
  text "BOARD #:" at 52.019,-42.054 h1.52
  text ".PRJ_Number" at 65.875,-42.054 h1.52
  text "REV:" at 87.325,-42.054 h1.52
  text ".PCB_Rev" at 94.729,-42.054 h1.52
  text "SVN REV:" at 108.61,-42.054 h1.52
  text ".VersionControl_RevNumber" at 121.463,-42.054 h1.52
  text "TID #:" at 52.019,-47.219 h1.52
  text ".TID" at 65.875,-47.219 h1.52
  text "PLOT NAME =" at -10.884,-52.434 h1.52
  text ".plot_File_Name" at 9.576,-52.434 h1.52
  text "GENERATED    :" at 52.07,-52.434 h1.52
  text ".Print_Date" at 74.155,-52.434 h1.52
  text ".Print_Time" at 92.672,-52.434 h1.52
  text "TEXAS INSTRUMENTS" at 124.79,-52.434 h1.52
M6 Assembly Bottom:
  lines w0.254: -12.509,-43.874 155.181,-43.874 ; -12.459,-49.039 155.181,-49.039 ; 23.254,-54.369 23.254,-49.217 ; 39.052,-43.874 39.052,-38.71 ; 60.389,-43.874 60.389,-38.71 ; 92.57,-54.204 92.57,-38.71 ; 115.151,-54.204 155.169,-54.204 155.169,-38.71 -12.509,-38.71 -12.509,-54.204 53.454,-54.204 155.181,-54.204 155.181,-38.71
  text "COMPONENTS MARKED 'DNP' SHOULD NOT BE POPULATED." at 149.911,-33.477 h1.52
  text ".VariantName" at 123.393,-36.424 h1.52
  text "ASSEMBLY VARIANT:" at 149.784,-36.424 h1.52
  text ".VersionControl_RevNumber" at 21.222,-42.067 h1.52
  text "SVN REV:" at 34.074,-42.067 h1.52
  text ".PCB_Rev" at 47.955,-42.067 h1.52
  text "REV:" at 55.359,-42.067 h1.52
  text ".PRJ_Number" at 76.81,-42.067 h1.52
  text "BOARD #:" at 90.665,-42.067 h1.52
  text "PCB VIEWED FROM BOTTOM SIDE" at 153.568,-42.067 h1.52
  text ".TID" at 76.81,-47.231 h1.52
  text "TID #:" at 90.665,-47.231 h1.52
  text "TEXAS INSTRUMENTS" at 17.894,-52.447 h1.52
  text ".Print_Time" at 50.013,-52.447 h1.52
  text ".Print_Date" at 68.529,-52.447 h1.52
  text "GENERATED    :" at 90.614,-52.447 h1.52
  text ".plot_File_Name" at 133.109,-52.447 h1.52
  text "PLOT NAME =" at 153.568,-52.447 h1.52
M9 Title Sheet:
  drawing of 57 lines, arcs and shapes, not listed
  text "1" at 13.712,178.727 h1.78
  text "2" at 77.102,178.727 h1.78
  text "3" at 140.331,178.727 h1.78
  text "4" at 204,178.727 h1.78
  text "5" at 267.475,178.727 h1.78
  text "6" at 331.102,178.727 h1.78
  text "A" at -15.659,149.695 h1.78
  text "A" at 360.261,149.695 h1.78
  text "B" at -15.659,89.243 h1.78
  text "B" at 360.261,89.243 h1.78
  text "C" at -15.659,28.918 h1.78
  text "C" at 360.261,28.918 h1.78
  text "PROJECT TITLE:" at 283.045,-18.351 h1.14
  text ".PRJ_Title" at 284.315,-21.738 h1.78
  text "DESIGNED FOR:" at 283.045,-25.997 h1.14
  text ".PRJ_Customer" at 284.315,-29.553 h1.78
  text "D" at -15.659,-31.28 h1.78
  text "D" at 360.261,-31.28 h1.78
  text "FILE NAME:" at 283.045,-33.617 h1.14
  text ".PCB_File_Name_No_Path" at 284.315,-36.665 h1.78
  text "Texas Instruments (TI) and/or its licensors do not warrant the accuracy or completeness of this specification" at 156.82,-40.776 h1.14
  text "ENGINEER:" at 283.045,-40.983 h1.14
  text "LAYOUT BY:" at 321.272,-40.983 h1.14
  text "or any information contained therein. TI and/or its licensors do not warrant that this design will meet" at 155.677,-43.637 h1.14
  text ".PRJ_Engineer" at 284.315,-44.92 h1.78
  text ".PCB_Layout" at 322.555,-44.92 h1.78
  text "the specifications, will be suitable for your application or fit for any particular purpose, or will operate in" at 155.677,-46.499 h1.14
  text ".Layer_Name" at 9.576,-47.206 h1.52
  text "ALTIUM DESIGNER VERSION:" at 321.272,-48.857 h1.14
  text "an implementation. TI and/or its licensors do not warrant that the design is production worthy. You should" at 155.677,-49.361 h1.14
  text "completely validate and test your design implementation to confirm the system functionality for your application." at 156.82,-52.222 h1.14
  text ".print_Scale" at 284.315,-52.243 h1.78
  text ".Application_BuildNumber" at 322.555,-52.243 h1.78
  text "1" at 13.712,-57.493 h1.78
  text "2" at 77.102,-57.493 h1.78
  text "3" at 140.331,-57.493 h1.78
  text "4" at 204,-57.493 h1.78
  text "5" at 267.475,-57.493 h1.78
  text "6" at 331.102,-57.493 h1.78
M10 Fab Notes:
  drawing of 189 lines, arcs and shapes, not listed
  text "DESIGN INFORMATION" at 309.423,136.047 h1.52
  text "MIN. TRACK WIDTH:" at 293.051,132.691 h1.52
  text "0.16" at 318.8,132.7 h1.52
  text "mm" at 324.827,132.691 h1.52
  text "MIN. CLEARANCE:" at 293.051,129.538 h1.52
  text "0.1" at 319.372,129.538 h1.52
  text "mm" at 324.827,129.538 h1.52
  text "MIN. VIA PAD SIZE:" at 293.051,126.385 h1.52
  text "24" at 320.134,126.385 h1.52
  text "MIL" at 324.827,126.385 h1.52
  text "0.05mm (2MIL)" at 310.704,123.086 h1.52
  text "MINIMUM ANNULAR RING" at 284.689,122.877 h1.52
  text "EXTERNAL" at 328.688,122.877 h1.52
  text "PER" at 289.769,120.08 h1.52
  text "IPC-D-275 CLASS 2 LEVEL C" at 295.357,120.08 h1.52
  text "MIL, HOLES" at 333.158,117.528 h1.52
  text "+/-" at 323.19,117.309 h1.52
  text "+/-" at 344.881,117.309 h1.52
  text "REGISTRATION TOLERANCES:" at 284.689,117.282 h1.52
  text "METAL" at 315.163,117.282 h1.52
  text "5" at 329.799,117.283 h1.52
  text "3" at 350.957,117.283 h1.52
  text "MIL" at 353.91,117.282 h1.52
  text "HOLE SIZE TOLERANCE (UNLESS OTHERWISE SPECIFIED):" at 284.689,114.785 h1.52
  text "+/-" at 344.881,114.712 h1.52
  text "3" at 350.957,114.685 h1.52
  text "MIL" at 353.91,114.685 h1.52
  text "MATERIAL:" at 282.79,111.189 h1.52
  text "FR-4 High Tg" at 307.846,107.924 h1.52
  text "X" at 304.177,107.722 h1.52
  text "FR-408" at 293.483,107.607 h1.52
  text "OTHER" at 331.278,107.607 h1.52
  text "62 MIL (1.6mm) +/-10%" at 301.614,103.974 h1.52
  text "X" at 298.563,103.912 h1.52
  text "THICKNESS:" at 284.689,103.765 h1.52
  text "OTHER" at 334.25,103.765 h1.52
  text "TOLERANCE:" at 284.689,100.252 h1.52
  text "X" at 306.234,100.252 h1.52
  text "ANSI IPC-6012 TYPE 3 CLASS 2" at 310.756,100.252 h1.52
  text "OTHER +/-" at 310.755,96.589 h1.52
  text "BOW & TWIST:" at 284.689,92.902 h1.52
  text "X" at 306.234,92.902 h1.52
  text "ANSI IPC-6012 TYPE 3 CLASS 2" at 310.756,92.902 h1.52
  text "OTHER +/-" at 310.755,89.176 h1.52
  text "DRILLING:" at 282.79,85.858 h1.52
  text "NC_DRILL FILES" at 327.519,83.186 h1.52
  text "REFERENCE:" at 284.689,83.086 h1.52
  text "X" at 301.383,83.084 h1.52
  text "AS SHOWN" at 305.904,83.086 h1.52
  text "X" at 324.268,83.086 h1.52
  text "OTHER" at 335.088,79.473 h1.52
  text "PTH COPPER THICKNESS:" at 284.681,79.383 h1.52
  text "X" at 313.617,79.383 h1.52
  text "20-30 um" at 316.868,79.383 h1.52
  text "BOARD FINISH:" at 282.79,75.634 h1.52
  text "SILKSCREEN:" at 286.732,72.837 h1.52
  text "X" at 311.06,72.837 h1.52
  text "TOP" at 314.032,72.837 h1.52
  text "X" at 324.014,72.837 h1.52
  text "BOTTOM" at 327.011,72.837 h1.52
  text "SILKSCREEN COLOR:" at 286.732,68.895 h1.52
  text "X" at 311.035,68.895 h1.52
  text "WHITE" at 314.032,68.895 h1.52
  text "OTHER" at 327.011,68.895 h1.52
  text "X" at 314.362,65.252 h1.52
  text "GREEN" at 317.359,65.252 h1.52
  text "OTHER" at 333.056,65.252 h1.52
  text "SOLDER RESIST COLOR:" at 286.732,65.077 h1.52
  text "X" at 314.362,61.334 h1.52
  text "MATTE" at 317.359,61.334 h1.52
  text "SEMI-GLOSS" at 333.045,61.317 h1.52
  text "IMMERSION GOLD (ENIG)" at 309.739,56.945 h1.52
  text "ENEPIG" at 343.713,56.762 h1.52
  text "SURFACE FINISH:" at 282.79,56.736 h1.52
  text "X" at 305.218,56.736 h1.52
  text "IMM. TIN/SILVER OR EQUIV" at 291.16,53.249 h1.52
  text "OTHER" at 327.519,53.149 h1.52
  text "ARRAY/PANEL:" at 282.79,49.202 h1.52
  text "CUT AND TRIM PER M1 BOARD OUTLINE" at 309.739,48.993 h1.52
  text "N.C. ROUTE" at 309.739,45.54 h1.52
  text "X" at 327.215,45.54 h1.52
  text "V. SCORE" at 331.736,45.54 h1.52
  text "CERTIFICATION:" at 282.79,42.26 h1.52
  text "MATERIALS AND WORKMANSHIP FOR ALL PCBS" at 301.205,42.26 h1.52
  text "TO MEET OR EXCEED THE REQUIREMENTS OF:" at 301.205,39.871 h1.52
  text "X" at 291.998,36.603 h1.52
  text "ANSI IPC-A-600F CLASS ->" at 295.249,36.603 h1.52
  text "X" at 337.108,36.603 h1.52
  text "2" at 339.902,36.603 h1.52
  text "1" at 331.901,36.565 h1.52
  text "3" at 348.893,36.565 h1.52
  text "X" at 312.622,32.852 h1.52
  text "RoHS" at 315.873,32.852 h1.52
  text "OTHER" at 332.241,32.852 h1.52
  text "PER ORDER" at 342.327,32.852 h1.52
  text "ALL BOARDS MUST MEET OR EXCEED UL94-V0 REQUIREMENTS." at 283.489,28.945 h1.52
  text "PCB MUST BEAR THE UL94V-0 UL REGISTERED MATERIAL ID NUMBER" at 283.489,25.997 h1.52
  text "ADDITIONAL REQUIREMENTS:" at 282.79,21.694 h1.52
  text "MICROSECTION:" at 284.689,18.973 h1.52
  text "YES" at 307.695,18.973 h1.52
  text "REQUIRED" at 329.577,15.307 h1.52
  text "BARE BOARD ELEC. TEST:" at 284.689,15.234 h1.52
  text "NONE" at 317.855,15.234 h1.52
  text "X" at 326.58,15.234 h1.52
  text "PER ORDER" at 344.613,15.234 h1.52
  text "XX MIL VIAS REQUIRE NON-CONDUCTIVE FILL AND PLANARIZE" at 288.96,10.028 h1.5
  text "XX MIL VIAS REQUIRE CONDUCTIVE FILL AND PLANARIZE" at 289.163,7.387 h1.52
  text "OUTER XX MIL TRACES REQUIRE 50 OHM SINGLE-ENDED IMPEDANCE" at 289.138,3.237 h1.47
  text "LAYER 2 & 3 (INNER LAYERS) XX MIL WIDE, XX MIL SPACE / TRACES REQUIRE 100 OHM DIFFERENTIAL IMPEDANCE" at 288.935,-2.75 h1.52
  text ".Layer_Name" at 9.576,-47.206 h1.52
M11 Gerber Information:
  lines w0.254: -12.497,-49.026 155.143,-49.026 ; -12.497,-43.862 155.194,-43.862 ; -12.497,-38.697 -12.497,-54.191 89.23,-54.191 155.194,-54.191 155.194,-38.697 -12.484,-38.697 -12.484,-54.191 27.534,-54.191 ; 50.114,-54.191 50.114,-38.697 ; 82.296,-43.862 82.296,-38.697 ; 103.632,-43.862 103.632,-38.697 ; 119.431,-54.356 119.431,-49.204
  text "ALL ARTWORK VIEWED FROM TOP SIDE" at -10.884,-42.054 h1.52
  text "BOARD #:" at 52.019,-42.054 h1.52
  text ".PRJ_Number" at 65.875,-42.054 h1.52
  text "REV:" at 87.325,-42.054 h1.52
  text ".PCB_Rev" at 94.729,-42.054 h1.52
  text "SVN REV:" at 108.61,-42.054 h1.52
  text ".VersionControl_RevNumber" at 121.463,-42.054 h1.52
  text "LAYER NAME =" at -10.884,-47.206 h1.52
  text "TID #:" at 52.019,-47.219 h1.52
  text ".TID" at 65.875,-47.219 h1.52
  text "PLOT NAME =" at -10.884,-52.434 h1.52
  text ".plot_File_Name" at 9.576,-52.434 h1.52
  text "GENERATED    :" at 52.07,-52.434 h1.52
  text ".Print_Date" at 74.155,-52.434 h1.52
  text ".Print_Time" at 92.672,-52.434 h1.52
  text "TEXAS INSTRUMENTS" at 124.79,-52.434 h1.52
M12 Stackup:
  drawing of 529 lines, arcs and shapes, not listed
  text "Layer" at 154.703,173.524 h1.52
  text "Name" at 165.115,173.524 h1.52
  text "Material" at 198.888,173.524 h1.52
  text "Thickness" at 219.456,173.524 h1.52
  text "Constant" at 235.962,173.524 h1.52
  text "Board Layer Stack" at 250.436,173.524 h1.52
  text "Top Overlay" at 165.115,170.476 h1.52
  text "Top Solder" at 165.115,167.428 h1.52
  text "SM-001" at 198.888,167.428 h1.52
  text "0.025mm" at 219.456,167.428 h1.52
  text "4" at 235.962,167.428 h1.52
  text "Top Surface Finish" at 165.115,164.38 h1.52
  text "Nickel, Gold" at 198.888,164.38 h1.52
  text "0.004mm" at 219.456,164.38 h1.52
  text "1" at 154.703,161.332 h1.52
  text "Top Layer" at 165.115,161.332 h1.52
  text "CF-004" at 198.888,161.332 h1.52
  text "0.035mm" at 219.456,161.332 h1.52
  text "Dielectric 1" at 165.115,158.284 h1.52
  text "PP-015" at 198.888,158.284 h1.52
  text "0.112mm" at 219.456,158.284 h1.52
  text "4.3" at 235.962,158.284 h1.52
  text "Dielectric 2" at 165.115,155.236 h1.52
  text "PP-008" at 198.888,155.236 h1.52
  text "0.079mm" at 219.456,155.236 h1.52
  text "4.1" at 235.962,155.236 h1.52
  text "2" at 154.703,152.188 h1.52
  text "Int1 (Sign)" at 165.115,152.188 h1.52
  text "CF-003" at 198.888,152.188 h1.52
  text "0.018mm" at 219.456,152.188 h1.52
  text "Dielectric 3" at 165.115,149.14 h1.52
  text "Core-034" at 198.888,149.14 h1.52
  text "0.406mm" at 219.456,149.14 h1.52
  text "4.6" at 235.962,149.14 h1.52
  text "3" at 154.703,146.092 h1.52
  text "Int2 (PWR)" at 165.115,146.092 h1.52
  text "CF-003" at 198.888,146.092 h1.52
  text "0.018mm" at 219.456,146.092 h1.52
  text "Dielectric 4" at 165.115,143.044 h1.52
  text "PP-010" at 198.888,143.044 h1.52
  text "0.086mm" at 219.456,143.044 h1.52
  text "4" at 235.962,143.044 h1.52
  text "Dielectric 5" at 165.115,139.996 h1.52
  text "PP-010" at 198.888,139.996 h1.52
  text "0.086mm" at 219.456,139.996 h1.52
  text "4" at 235.962,139.996 h1.52
  text "4" at 154.703,136.948 h1.52
  text "Int3 (GND)" at 165.115,136.948 h1.52
  text "CF-003" at 198.888,136.948 h1.52
  text "0.018mm" at 219.456,136.948 h1.52
  text "Dielectric 6" at 165.115,133.9 h1.52
  text "Core-034" at 198.888,133.9 h1.52
  text "0.406mm" at 219.456,133.9 h1.52
  text "4.6" at 235.962,133.9 h1.52
  text "5" at 154.703,130.852 h1.52
  text "Int4 (Sign)" at 165.115,130.852 h1.52
  text "CF-003" at 198.888,130.852 h1.52
  text "0.018mm" at 219.456,130.852 h1.52
  text "Dielectric 7" at 165.115,127.804 h1.52
  text "PP-008" at 198.888,127.804 h1.52
  text "0.079mm" at 219.456,127.804 h1.52
  text "4.1" at 235.962,127.804 h1.52
  text "Dielectric 8" at 165.115,124.756 h1.52
  text "PP-015" at 198.888,124.756 h1.52
  text "0.112mm" at 219.456,124.756 h1.52
  text "4.3" at 235.962,124.756 h1.52
  text "6" at 154.703,121.708 h1.52
  text "Bottom Layer" at 165.115,121.708 h1.52
  text "CF-004" at 198.888,121.708 h1.52
  text "0.035mm" at 219.456,121.708 h1.52
  text "Bottom Surface Finish" at 165.115,118.66 h1.52
  text "Nickel, Gold" at 198.888,118.66 h1.52
  text "0.004mm" at 219.456,118.66 h1.52
  text "Bottom Solder" at 165.115,115.612 h1.52
  text "SM-001" at 198.888,115.612 h1.52
  text "0.025mm" at 219.456,115.612 h1.52
  text "4" at 235.962,115.612 h1.52
  text "Bottom Overlay" at 165.115,112.564 h1.52
  text "Total board thickness:" at 154.703,109.516 h1.52
  text "1.567mm" at 219.456,109.516 h1.52
  text ".Layer_Name" at 9.576,-47.206 h1.52
M13 Component Bodies Top:
  text ".Layer_Name" at 9.576,-47.206 h1.52
M14 Component Bodies Bottom:
  text ".Layer_Name" at 9.576,-47.206 h1.52
M15 Courtyards Top:
  text ".Layer_Name" at 9.576,-47.206 h1.52
M16 Courtyards Bottom:
  text ".Layer_Name" at 9.576,-47.206 h1.52
Drill Drawing:
  text ".Layer_Name" at 9.576,-47.206 h1.52
M17 Embedded Cavity:
  text ".Layer_Name" at 9.576,-47.206 h1.52
M18 Embedded Assembly:
  text ".Layer_Name" at 9.576,-47.206 h1.52
M19 Embedded Keepout:
  text ".Layer_Name" at 9.576,-47.206 h1.52

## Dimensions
0,0 to 19.812,105.918 on M2 Board Dimensions
178.809,21.588 to 217.796,14 on M2 Board Dimensions
178.809,21.588 to 164.796,14 on M2 Board Dimensions
122.809,21.588 to 161.496,14 on M2 Board Dimensions
122.809,21.588 to 108.496,14 on M2 Board Dimensions
66.809,21.588 to 105.196,14 on M2 Board Dimensions
66.809,21.588 to 52.196,14 on M2 Board Dimensions
50.546,6.096 to 219.456,6.096 on M2 Board Dimensions
270.002,2.54 to 0,0 on M2 Board Dimensions
0,-19.35 to 25.4,-19.35 on M2 Board Dimensions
